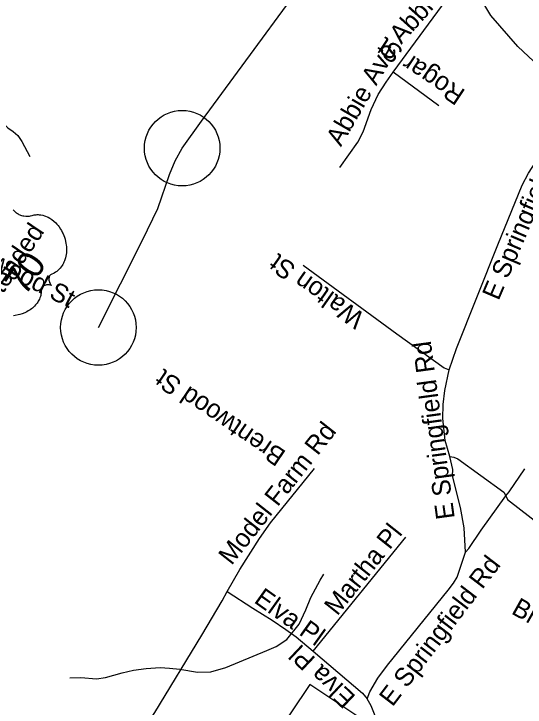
# Model space of a CAD drawing. Extents: x 1715610 to 1720914, y 798298 to 802505.
# Drawn here: x 1715906.1 to 1715962.9, y 799408.2 to 799485.2 of the extents above; entities that cross this region are included whole.
import ezdxf

# ---------------------------------------------------------------- set-up
doc = ezdxf.new("R2010")
doc.units = 0
doc.layers.add('Default', color=7, linetype='Continuous')
doc.layers.add('Prop DSN Text', color=7, linetype='Continuous')

msp = doc.modelspace()

# ---------------------------------------------------------------- linework, layer by layer
at = {"layer": 'Default'}
for p, q in [((1715953.354, 799474.985), (1715948.254, 799478.735)), ((1715939.358, 799414.374), (1715949.684, 799427.063)), ((1715955.382, 799422.594), (1715956.301, 799425.395))]:
    msp.add_line(p, q, dxfattribs=at)
for points in [[(1716023.718, 799419.386), (1716016.126, 799426.487), (1716009.969, 799432.19), (1716003.784, 799437.668), (1715996.928, 799443.961), (1715992.338, 799448.007), (1715990.609, 799449.635), (1715988.316, 799452.217), (1715982.034, 799460.209), (1715980.122, 799463.74), (1715978.992, 799465.379), (1715977.581, 799467.165), (1715976.083, 799468.756), (1715974.189, 799470.715), (1715970.305, 799473.958), (1715962.149, 799481.58), (1715959.118, 799485.028), (1715957.834, 799487.223), (1715956.743, 799489.456), (1715954.262, 799498.464), (1715953.463, 799502.756), (1715953.361, 799508.585), (1715955.096, 799517.509), (1715956.471, 799526.044)], [(1715915.48, 799450.355), (1715920.398, 799460.057), (1715922.102, 799463.589), (1715923.37, 799467.369), (1715924.004, 799468.869), (1715924.795, 799470.289), (1715926.931, 799473.286), (1715942.26, 799494.135), (1715943.397, 799495.085), (1715944.774, 799495.776), (1715952.083, 799497.604), (1715954.539, 799498.123)], [(1715893.124, 799489.898), (1715893.538, 799489.191), (1715894.333, 799487.965), (1715895.142, 799486.989), (1715896.43, 799485.48), (1715897.536, 799484.09), (1715898.57, 799482.595), (1715899.375, 799481.306), (1715899.849, 799480.457), (1715900.368, 799479.364), (1715900.838, 799478.357), (1715901.908, 799476.836), (1715904.274, 799473.744), (1715904.834, 799473.098), (1715905.406, 799472.549), (1715905.984, 799472.157), (1715906.509, 799471.693), (1715906.948, 799471.023), (1715907.858, 799469.346)], [(1715948.254, 799478.735), (1715954.691, 799487.47), (1715956.39, 799488.718), (1715957.146, 799489.036)], [(1715942.318, 799468.123), (1715944.335, 799470.941), (1715944.945, 799472.11), (1715945.802, 799474.599), (1715946.598, 799476.251), (1715947.473, 799477.641), (1715948.254, 799478.735)], [(1715954.479, 799445.642), (1715955.299, 799448.004), (1715959.91, 799459.535), (1715962.603, 799466.183), (1715963.312, 799467.501), (1715964.117, 799468.785), (1715965.444, 799470.223), (1715968.726, 799472.878), (1715970.531, 799473.851)], [(1715906.001, 799463.45), (1715906.08, 799463.356), (1715906.15, 799463.283), (1715906.307, 799463.145), (1715906.385, 799463.085), (1715906.465, 799463.031), (1715906.553, 799462.978), (1715906.64, 799462.932), (1715906.735, 799462.889), (1715906.819, 799462.853), (1715906.927, 799462.815), (1715907.057, 799462.778), (1715907.188, 799462.751), (1715907.414, 799462.727), (1715907.66, 799462.726), (1715907.809, 799462.742), (1715907.944, 799462.767), (1715908.123, 799462.819), (1715908.223, 799462.845), (1715908.346, 799462.869), (1715908.566, 799462.896), (1715908.664, 799462.901), (1715908.771, 799462.901), (1715908.878, 799462.895), (1715908.99, 799462.886), (1715909.086, 799462.874), (1715909.295, 799462.832), (1715909.488, 799462.774), (1715909.588, 799462.74), (1715909.8, 799462.65), (1715909.902, 799462.601), (1715910.096, 799462.493), (1715910.319, 799462.345), (1715910.519, 799462.186), (1715910.738, 799461.982), (1715910.864, 799461.85), (1715911.001, 799461.685), (1715911.117, 799461.537), (1715911.278, 799461.302), (1715911.385, 799461.118), (1715911.503, 799460.893), (1715911.569, 799460.748), (1715911.636, 799460.587), (1715911.706, 799460.393), (1715911.775, 799460.177), (1715911.836, 799459.931), (1715911.874, 799459.739), (1715911.907, 799459.5), (1715911.922, 799459.359), (1715911.933, 799459.164), (1715911.932, 799458.908), (1715911.916, 799458.666), (1715911.893, 799458.467), (1715911.862, 799458.297), (1715911.812, 799458.084), (1715911.701, 799457.747), (1715911.653, 799457.63), (1715911.589, 799457.495), (1715911.524, 799457.373), (1715911.456, 799457.257), (1715911.356, 799457.108), (1715911.245, 799456.966), (1715911.131, 799456.839), (1715911.002, 799456.714), (1715910.854, 799456.591), (1715910.707, 799456.488), (1715910.543, 799456.394), (1715910.234, 799456.257), (1715910.152, 799456.212), (1715910.116, 799456.18), (1715910.05, 799456.092), (1715910.011, 799455.993), (1715909.987, 799455.881), (1715909.979, 799455.809), (1715909.978, 799455.707), (1715909.985, 799455.623), (1715910.003, 799455.516), (1715910.025, 799455.436), (1715910.043, 799455.374), (1715910.104, 799455.236), (1715910.138, 799455.179), (1715910.186, 799455.111), (1715910.266, 799455.025), (1715910.126, 799455.075), (1715910.023, 799455.093), (1715909.927, 799455.098), (1715909.839, 799455.096), (1715909.717, 799455.08), (1715909.619, 799455.059), (1715909.511, 799455.026), (1715909.413, 799454.98), (1715909.34, 799454.939), (1715909.28, 799454.897), (1715909.217, 799454.839), (1715909.174, 799454.785), (1715909.144, 799454.738), (1715909.116, 799454.664), (1715909.12, 799454.536), (1715909.122, 799454.415), (1715909.118, 799454.289), (1715909.103, 799454.144), (1715909.087, 799454.041), (1715909.061, 799453.924), (1715909.025, 799453.791), (1715908.976, 799453.652), (1715908.919, 799453.515), (1715908.864, 799453.397), (1715908.798, 799453.275), (1715908.732, 799453.17), (1715908.659, 799453.063), (1715908.584, 799452.967), (1715908.495, 799452.857), (1715908.376, 799452.726), (1715908.269, 799452.624), (1715908.15, 799452.52), (1715908.021, 799452.417), (1715907.875, 799452.313), (1715907.682, 799452.189), (1715907.538, 799452.11), (1715907.299, 799451.992), (1715906.994, 799451.871), (1715906.743, 799451.794), (1715906.547, 799451.745), (1715906.239, 799451.686), (1715906.046, 799451.661)], [(1715938.258, 799457.274), (1715948.676, 799449.644), (1715953.95, 799445.864), (1715954.479, 799445.642)], [(1715954.564, 799436.015), (1715954.048, 799437.804), (1715953.807, 799440.232), (1715953.835, 799441.806), (1715954.014, 799443.335), (1715954.479, 799445.642)], [(1715954.564, 799436.015), (1715955.01, 799435.936), (1715955.454, 799435.744), (1715960.592, 799432.062), (1715960.791, 799431.641)], [(1715956.301, 799425.395), (1715956.164, 799428.074), (1715955.748, 799430.326), (1715954.863, 799433.855), (1715954.916, 799434.55), (1715954.564, 799436.015)], [(1715929.796, 799421.006), (1715931.198, 799423.47), (1715933.384, 799426.892), (1715934.621, 799428.625), (1715939.509, 799434.668)], [(1715960.791, 799431.641), (1715961.168, 799432.089), (1715962.904, 799434.624)], [(1715956.301, 799425.395), (1715956.678, 799425.781), (1715958.039, 799427.837), (1715960.791, 799431.641)], [(1715960.791, 799431.641), (1715960.978, 799431.241), (1715966.264, 799427.141)], [(1715912.321, 799411.391), (1715913.528, 799411.463), (1715915.252, 799411.286), (1715916.257, 799411.443), (1715918.132, 799411.953), (1715919.391, 799412.253), (1715920.793, 799412.453), (1715922.338, 799412.557), (1715923.388, 799412.474), (1715924.534, 799412.378), (1715926.508, 799412.028), (1715927.969, 799412.083), (1715929.664, 799412.558), (1715934.223, 799414.45), (1715935.267, 799414.897), (1715936.435, 799415.682), (1715937.804, 799417.379), (1715938.571, 799418.964), (1715939.093, 799420.345), (1715940.14, 799422.264), (1715940.546, 799422.934)], [(1715945.36, 799409.087), (1715945.68, 799409.841), (1715946.574, 799411.373), (1715947.62, 799412.816), (1715954.368, 799421.16), (1715954.971, 799421.95), (1715955.382, 799422.594)], [(1715913.434, 799396.265), (1715919.268, 799403.798), (1715920.318, 799405.379), (1715921.745, 799407.57), (1715926.981, 799416.155), (1715929.26, 799419.958), (1715929.796, 799421.006)], [(1715929.796, 799421.006), (1715932.655, 799419.151), (1715934.818, 799417.825), (1715936.322, 799416.799), (1715937.469, 799415.956), (1715939.358, 799414.374)], [(1715939.358, 799414.374), (1715944.857, 799409.692), (1715945.36, 799409.087)], [(1715948.14, 799401.8), (1715947.848, 799402.296), (1715947.286, 799404.596), (1715945.804, 799408.283), (1715945.36, 799409.087)]]:
    msp.add_lwpolyline(points, dxfattribs=at)
msp.add_lwpolyline([(1715938.992, 799410.675), (1715928.51, 799395.014), (1715935.3, 799390.469), (1715945.782, 799406.13)], close=True, dxfattribs=at)
at = {"layer": 'Prop DSN Text'}
for centre in [(1715924.795, 799470.289), (1715915.48, 799450.355)]:
    msp.add_circle(centre, 4.2, dxfattribs=at)

# ---------------------------------------------------------------- texts
at = {"layer": 'Default'}
for s, height, rotation, p in [('Abbie Ave', 2.0663, 48.06984, (1715949.168, 799481.769)), ('Abbie Ave', 2.0663, 59.91985, (1715942.456, 799470.378)), ('Rogar St', 2.0663, 146.20506, (1715956.423, 799476.661)), ('E Springfield Rd', 2.06625, 66.8835, (1715959.984, 799453.262)), ('Brentwood Extended', 2.06625, 56.20506, (1715895.278, 799439.725)), ('Brentwood St', 2.06625, 332.62893, (1715897.473, 799460.122)), ('70', 2.9906, 56.20506, (1715907.327, 799453.767)), ('Walton St', 2.0663, 144.83275, (1715945.243, 799451.762)), ('E Springfield Rd', 2.06625, 97.74788, (1715955.126, 799429.161)), ('Brentwood St', 2.06625, 145.8831, (1715936.464, 799436.52)), ('Model Farm Rd', 2.06625, 51.85229, (1715930.289, 799423.832)), ('Martha Pl', 2.0663, 51.57754, (1715942.049, 799418.225)), ('E Springfield Rd', 2.06625, 52.59426, (1715948.191, 799408.11)), ('Elva Pl', 2.0663, 324.52668, (1715932.682, 799419.847)), ('Brentwood St', 2.06625, 330.67743, (1715961.303, 799418.6)), ('Elva Pl', 2.0663, 136.68745, (1715944.203, 799409.333))]:
    msp.add_text(s, height=height, rotation=rotation, dxfattribs=at).set_placement(p)

doc.saveas('drawing.dxf')
